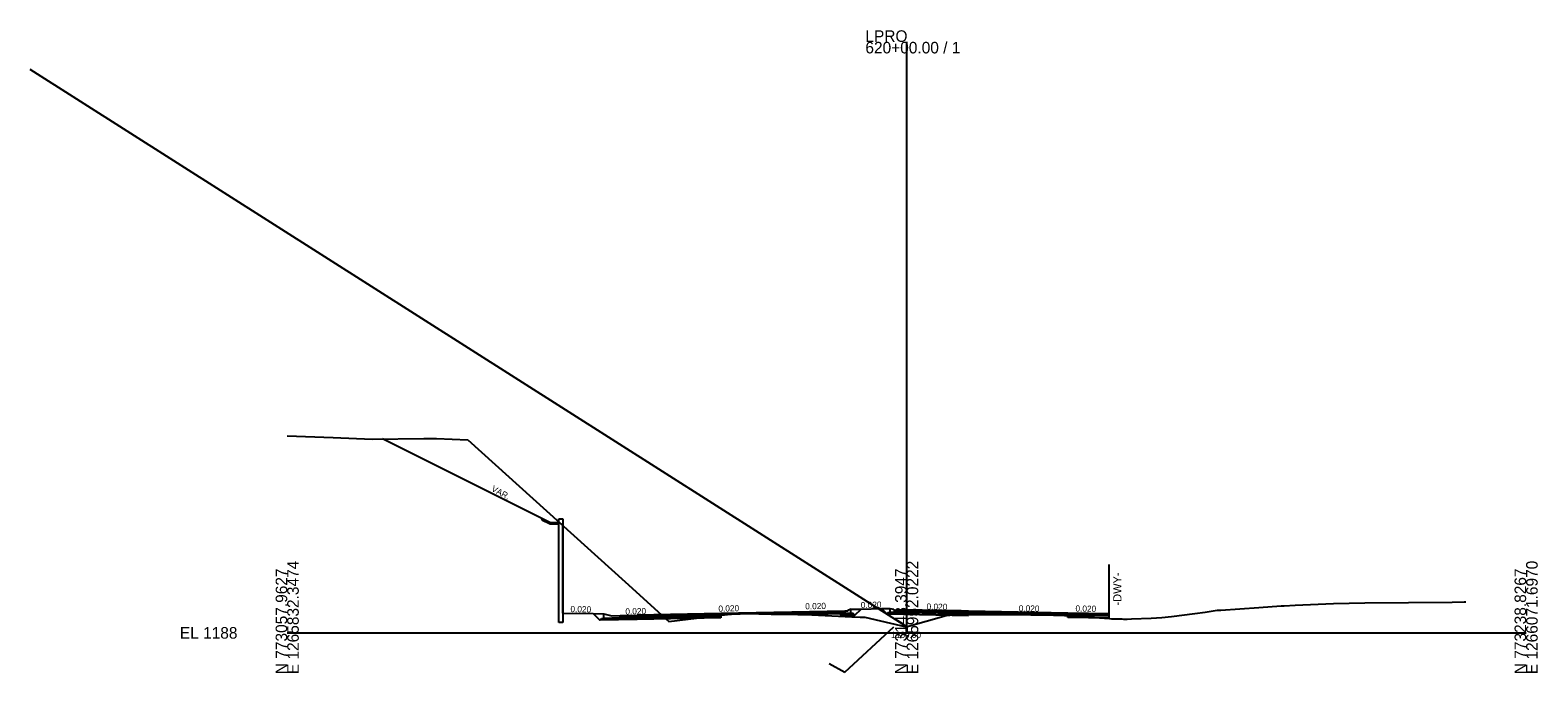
# Model space of a CAD drawing. Extents: x -3833 to 1267678, y -522 to 773248.
# Drawn here: x 2937.8 to 3302.8, y 990.3 to 1146.1 of the extents above; entities that cross this region are included whole.
import ezdxf

# ---------------------------------------------------------------- set-up
doc = ezdxf.new("R2010")
doc.units = 0
for name, color, linetype in [('Exist Cross Section Cell', 7, 'Continuous'), ('Exist XS Center Line Elevation Label', 7, 'Continuous'), ('Exist XS Ground Line', 7, 'Continuous'), ('Prop CMT DNC', 7, 'Continuous'), ('Prop CMT Pvmt Course 1', 7, 'Continuous'), ('Prop CMT Pvmt Course 2', 7, 'Continuous'), ('Prop CMT Pvmt Course 3', 7, 'Continuous'), ('Prop CMT Pvmt Course 4', 7, 'Continuous'), ('Prop CMT Shld Paved Course 1', 7, 'Continuous'), ('Prop CMT Shld Paved Course 2', 7, 'Continuous'), ('Prop CMT Shld Paved Course 4', 7, 'Continuous'), ('Prop CMT Slope Grass', 7, 'Continuous'), ('Prop CMT Subgrade Earthwork', 7, 'Continuous'), ('Prop Conc Curb and Gutter', 7, 'Continuous'), ('Prop Conc Island Cover', 7, 'Continuous'), ('Prop Corridor Mesh Bottom', 7, 'Continuous'), ('Prop XS Ditch Slope Text', 7, 'Continuous'), ('Prop XS Finish Grade', 7, 'Continuous'), ('Prop XS Label Text', 7, 'Continuous'), ('Prop XS SE Text', 7, 'Continuous'), ('Prop XS Shear Point Element', 7, 'Continuous'), ('Prop XS Shear Point Label', 7, 'Continuous'), ('Scratch_Level_1', 7, 'Continuous'), ('Scratch_Level_5', 7, 'Continuous')]:
    doc.layers.add(name, color=color, linetype=linetype)

msp = doc.modelspace()

# ---------------------------------------------------------------- linework, layer by layer
at = {"layer": 'Exist Cross Section Cell'}
for p, q in [((3150, 1000), (3150, 1143.25)), ((3000, 1000), (3150, 1000)), ((3150, 1000), (3300, 1000))]:
    msp.add_line(p, q, dxfattribs=at)
at = {"layer": 'Exist XS Ground Line'}
for p, q in [((3000, 1047.75), (3011.14, 1047.33)), ((3011.14, 1047.33), (3020.61, 1046.99)), ((3020.61, 1046.99), (3033.09, 1047.12)), ((3033.09, 1047.12), (3036.11, 1047.09)), ((3036.11, 1047.09), (3043.76, 1046.75)), ((3043.76, 1046.75), (3081.86, 1012.39)), ((3081.86, 1012.39), (3092.43, 1002.74)), ((3097.05, 1003.31), (3107.29, 1004.55)), ((3107.29, 1004.55), (3109.1, 1004.6)), ((3109.1, 1004.6), (3111.2, 1004.66)), ((3111.2, 1004.66), (3117.18, 1004.57)), ((3117.18, 1004.57), (3123.93, 1004.46)), ((3123.93, 1004.46), (3127.07, 1004.35)), ((3127.07, 1004.35), (3136.72, 1003.92)), ((3149.84, 1001.46), (3159.58, 1004.21)), ((3159.58, 1004.21), (3160.47, 1004.3)), ((3160.47, 1004.3), (3163.04, 1004.39)), ((3163.04, 1004.39), (3163.99, 1004.42)), ((3163.99, 1004.42), (3173.1, 1004.49)), ((3173.1, 1004.49), (3176.01, 1004.49)), ((3176.01, 1004.49), (3185.56, 1004.26)), ((3185.56, 1004.26), (3188.2, 1004.19)), ((3188.2, 1004.19), (3199.08, 1003.48)), ((3214.11, 1003.98), (3219.76, 1004.67)), ((3219.76, 1004.67), (3222.29, 1005)), ((3222.29, 1005), (3224.73, 1005.42)), ((3224.73, 1005.42), (3225.22, 1005.48)), ((3225.22, 1005.48), (3226.1, 1005.53)), ((3226.1, 1005.53), (3235.25, 1006.18)), ((3235.25, 1006.18), (3240.68, 1006.53)), ((3240.68, 1006.53), (3241.44, 1006.56)), ((3241.44, 1006.56), (3244.07, 1006.68)), ((3244.07, 1006.68), (3253.37, 1007.09)), ((3253.37, 1007.09), (3260.93, 1007.25)), ((3260.93, 1007.25), (3282.07, 1007.46)), ((3282.07, 1007.46), (3285.03, 1007.5)), ((3285.03, 1007.5), (3285.44, 1007.51)), ((3092.43, 1002.74), (3097.05, 1003.31)), ((3136.72, 1003.92), (3137.2, 1003.89)), ((3137.2, 1003.89), (3138.77, 1003.77)), ((3138.77, 1003.77), (3139.86, 1003.77)), ((3139.86, 1003.77), (3149.84, 1001.46)), ((3199.08, 1003.48), (3199.63, 1003.44)), ((3199.63, 1003.44), (3202.11, 1003.4)), ((3202.11, 1003.4), (3202.53, 1003.36)), ((3202.53, 1003.36), (3203.38, 1003.35)), ((3203.38, 1003.35), (3204.48, 1003.4)), ((3204.48, 1003.4), (3209.22, 1003.53)), ((3209.22, 1003.53), (3211.8, 1003.75)), ((3211.8, 1003.75), (3214.11, 1003.98))]:
    msp.add_line(p, q, dxfattribs=at)
at = {"layer": 'Prop CMT Pvmt Course 1'}
for p, q in [((3135, 1005.28), (3105, 1004.68)), ((3105, 1004.68), (3105, 1004.68)), ((3105, 1004.68), (3105, 1004.43)), ((3105, 1004.43), (3106.97, 1004.52)), ((3105, 1004.43), (3105, 1004.43)), ((3105, 1004.43), (3105, 1004.43)), ((3106.97, 1004.52), (3107.62, 1004.57)), ((3107.62, 1004.57), (3109.7, 1004.62)), ((3109.7, 1004.62), (3135, 1005.03)), ((3135, 1005.03), (3135, 1005.28)), ((3135, 1005.03), (3135, 1005.03)), ((3161.27, 1005.35), (3161.27, 1005.27)), ((3161.38, 1005.35), (3161.27, 1005.35)), ((3161.27, 1005.27), (3161.27, 1005.1)), ((3161.27, 1005.1), (3161.38, 1005.1)), ((3161.4, 1005.35), (3161.38, 1005.35)), ((3161.38, 1005.1), (3161.4, 1005.1)), ((3161.8, 1005.35), (3161.4, 1005.35)), ((3161.4, 1005.1), (3161.8, 1005.1)), ((3161.84, 1005.35), (3161.8, 1005.35)), ((3161.8, 1005.1), (3161.84, 1005.1)), ((3162.05, 1005.34), (3161.84, 1005.35)), ((3161.84, 1005.1), (3162.05, 1005.09)), ((3162.17, 1005.34), (3162.05, 1005.34)), ((3162.05, 1005.09), (3162.17, 1005.09)), ((3162.7, 1005.33), (3162.17, 1005.34)), ((3162.17, 1005.09), (3162.7, 1005.08)), ((3162.75, 1005.33), (3162.7, 1005.33)), ((3162.7, 1005.08), (3162.75, 1005.08)), ((3163.03, 1005.32), (3162.75, 1005.33)), ((3162.75, 1005.08), (3163.03, 1005.07)), ((3163.04, 1005.32), (3163.03, 1005.32)), ((3163.03, 1005.07), (3163.04, 1005.07)), ((3163.12, 1005.31), (3163.04, 1005.32)), ((3163.04, 1005.07), (3163.12, 1005.06)), ((3163.14, 1005.31), (3163.12, 1005.31)), ((3163.12, 1005.06), (3163.14, 1005.06)), ((3163.22, 1005.31), (3163.14, 1005.31)), ((3163.14, 1005.06), (3163.22, 1005.06)), ((3163.22, 1005.1), (3163.22, 1005.31)), ((3163.22, 1005.06), (3163.22, 1005.1)), ((3189, 1004.8), (3165, 1005.28)), ((3165, 1005.28), (3165, 1005.03)), ((3165, 1005.03), (3165, 1005.03)), ((3165, 1005.03), (3189, 1004.55)), ((3189, 1004.55), (3189, 1004.8)), ((3189, 1004.8), (3189, 1004.8)), ((3189, 1004.55), (3189, 1004.55)), ((3189, 1004.55), (3189, 1004.55))]:
    msp.add_line(p, q, dxfattribs=at)
at = {"layer": 'Prop CMT Pvmt Course 2'}
for p, q in [((3135, 1005.03), (3135, 1005.03)), ((3135, 1005.03), (3135, 1004.7)), ((3135, 1004.7), (3135, 1004.7)), ((3135, 1004.7), (3135, 1004.69)), ((3135, 1004.69), (3135, 1004.69)), ((3150, 1005.33), (3147.54, 1005.28)), ((3147.54, 1004.94), (3150, 1005)), ((3165, 1005.03), (3150, 1005.33)), ((3150, 1005), (3165, 1004.69)), ((3161.27, 1005.1), (3161.27, 1005.02)), ((3161.38, 1005.1), (3161.27, 1005.1)), ((3161.27, 1005.02), (3161.27, 1004.85)), ((3161.4, 1005.1), (3161.38, 1005.1)), ((3161.8, 1005.1), (3161.4, 1005.1)), ((3161.84, 1005.1), (3161.8, 1005.1)), ((3162.05, 1005.09), (3161.84, 1005.1)), ((3162.17, 1005.09), (3162.05, 1005.09)), ((3162.7, 1005.08), (3162.17, 1005.09)), ((3162.75, 1005.08), (3162.7, 1005.08)), ((3163.03, 1005.07), (3162.75, 1005.08)), ((3163.04, 1005.07), (3163.03, 1005.07)), ((3163.12, 1005.06), (3163.04, 1005.07)), ((3163.14, 1005.06), (3163.12, 1005.06)), ((3163.22, 1005.06), (3163.14, 1005.06)), ((3163.22, 1004.85), (3163.22, 1005.06)), ((3163.22, 1004.81), (3163.22, 1004.85)), ((3165, 1004.69), (3165, 1005.03)), ((3165, 1005.03), (3165, 1005.03)), ((3165, 1004.69), (3165, 1004.69)), ((3165, 1004.69), (3165, 1004.69)), ((3165, 1004.69), (3165, 1004.69))]:
    msp.add_line(p, q, dxfattribs=at)
at = {"layer": 'Prop CMT Pvmt Course 3'}
for p, q in [((3137.01, 1004.73), (3135, 1004.69)), ((3137.46, 1004.28), (3137.01, 1004.73)), ((3145.25, 1004.7), (3145.53, 1004.98)), ((3145.53, 1004.98), (3147.54, 1004.94)), ((3161.27, 1004.85), (3161.27, 1004.74)), ((3161.27, 1004.74), (3161.27, 1004.47)), ((3163.22, 1004.5), (3163.22, 1004.81)), ((3163.22, 1004.44), (3163.22, 1004.5))]:
    msp.add_line(p, q, dxfattribs=at)
at = {"layer": 'Prop CMT Pvmt Course 4'}
for p, q in [((3134, 1005.26), (3134, 1004.04)), ((3134, 1004.21), (3137.46, 1004.28)), ((3135, 1004.69), (3135, 1004.69)), ((3145.53, 1004.98), (3145.18, 1004.63)), ((3145.18, 1004.63), (3164.99, 1004.23)), ((3145.53, 1004.98), (3145.53, 1004.98)), ((3150, 1005), (3147.54, 1004.94)), ((3165, 1004.69), (3150, 1005)), ((3161.27, 1004.47), (3161.27, 1004.31)), ((3163.22, 1004.27), (3163.22, 1004.44)), ((3165, 1004.23), (3165, 1004.69)), ((3165, 1004.69), (3165, 1004.69)), ((3165, 1004.69), (3165, 1004.69))]:
    msp.add_line(p, q, dxfattribs=at)
at = {"layer": 'Prop CMT Shld Paved Course 1'}
for p, q in [((3080.64, 1004.19), (3084.74, 1004.27)), ((3080.64, 1003.94), (3080.64, 1004.19)), ((3080.64, 1004.19), (3080.64, 1004.19)), ((3084.74, 1004.02), (3080.64, 1003.94)), ((3105, 1004.68), (3084.74, 1004.27)), ((3084.74, 1004.02), (3105, 1004.43)), ((3084.74, 1004.27), (3084.74, 1004.02)), ((3084.74, 1004.27), (3084.74, 1004.02)), ((3084.74, 1004.02), (3084.74, 1004.02)), ((3105, 1004.43), (3105, 1004.68)), ((3135, 1005.28), (3135, 1005.28)), ((3135, 1005.28), (3135, 1005.03)), ((3135, 1005.03), (3135, 1005.03)), ((3135, 1005.03), (3135, 1005.03)), ((3150, 1005.58), (3147.54, 1005.53)), ((3147.54, 1005.28), (3150, 1005.33)), ((3165, 1005.28), (3150, 1005.58)), ((3150, 1005.33), (3165, 1005.03)), ((3165, 1005.03), (3165, 1005.28)), ((3165, 1005.28), (3165, 1005.28)), ((3165, 1005.03), (3165, 1005.03)), ((3165, 1005.03), (3165, 1005.03)), ((3199, 1004.6), (3189, 1004.8)), ((3080.64, 1003.94), (3080.64, 1003.94)), ((3080.64, 1003.94), (3080.64, 1003.94))]:
    msp.add_line(p, q, dxfattribs=at)
at = {"layer": 'Prop CMT Shld Paved Course 2'}
for p, q in [((3080.64, 1003.94), (3084.74, 1004.02)), ((3105, 1004.43), (3084.74, 1004.02)), ((3084.74, 1003.69), (3105, 1004.09)), ((3084.74, 1004.02), (3084.74, 1003.69)), ((3084.74, 1004.02), (3084.74, 1003.69)), ((3106.38, 1004.49), (3105, 1004.43)), ((3105, 1004.27), (3106.48, 1004.46)), ((3105, 1004.09), (3105, 1004.43)), ((3105, 1004.43), (3105, 1004.43)), ((3105, 1004.43), (3105, 1004.27)), ((3105, 1004.27), (3105, 1004.27)), ((3105, 1004.27), (3105, 1004.27)), ((3107.52, 1004.62), (3106.38, 1004.49)), ((3106.38, 1004.49), (3107.52, 1004.62)), ((3106.48, 1004.46), (3106.48, 1004.46)), ((3106.48, 1004.46), (3106.48, 1004.46)), ((3110.75, 1004.68), (3107.52, 1004.62)), ((3107.52, 1004.62), (3110.75, 1004.68)), ((3111.99, 1004.67), (3110.75, 1004.68)), ((3110.75, 1004.68), (3111.99, 1004.67)), ((3117.18, 1004.67), (3111.99, 1004.67)), ((3111.99, 1004.67), (3111.99, 1004.67)), ((3111.99, 1004.67), (3114.34, 1004.61)), ((3114.34, 1004.61), (3114.34, 1004.61)), ((3114.34, 1004.61), (3117.18, 1004.57)), ((3123.93, 1004.8), (3117.18, 1004.67)), ((3117.18, 1004.67), (3117.18, 1004.67)), ((3117.18, 1004.57), (3117.18, 1004.57)), ((3117.18, 1004.57), (3119.47, 1004.53)), ((3119.47, 1004.53), (3123.61, 1004.46)), ((3123.61, 1004.46), (3123.93, 1004.47)), ((3127.07, 1004.87), (3123.93, 1004.8)), ((3123.93, 1004.47), (3127.07, 1004.53)), ((3135, 1005.03), (3127.07, 1004.87)), ((3127.07, 1004.87), (3127.07, 1004.87)), ((3127.07, 1004.53), (3135, 1004.69)), ((3127.07, 1004.53), (3127.07, 1004.53)), ((3135, 1005.03), (3135, 1005.03)), ((3135, 1004.69), (3135, 1004.69)), ((3135, 1004.69), (3135, 1004.69)), ((3173.1, 1004.86), (3165, 1005.03)), ((3165, 1005.03), (3165, 1005.03)), ((3165, 1005.03), (3165, 1004.69)), ((3165, 1004.69), (3165, 1004.69)), ((3165, 1004.69), (3165, 1004.69)), ((3165, 1004.69), (3173.1, 1004.53)), ((3176.01, 1004.81), (3173.1, 1004.86)), ((3173.1, 1004.86), (3173.1, 1004.86)), ((3173.1, 1004.53), (3173.1, 1004.53)), ((3173.1, 1004.53), (3175.19, 1004.49)), ((3175.19, 1004.49), (3175.19, 1004.49)), ((3175.19, 1004.49), (3176.01, 1004.49)), ((3185.56, 1004.61), (3176.01, 1004.81)), ((3176.01, 1004.81), (3176.01, 1004.81)), ((3176.01, 1004.49), (3180.05, 1004.39)), ((3180.05, 1004.39), (3180.05, 1004.39)), ((3180.05, 1004.39), (3185.56, 1004.28)), ((3188.2, 1004.56), (3185.56, 1004.61)), ((3185.56, 1004.61), (3185.56, 1004.61)), ((3185.56, 1004.28), (3185.56, 1004.28)), ((3185.56, 1004.28), (3185.56, 1004.28)), ((3185.56, 1004.28), (3188.2, 1004.23)), ((3189, 1004.55), (3188.2, 1004.56)), ((3188.2, 1004.56), (3188.2, 1004.56)), ((3188.2, 1004.23), (3188.2, 1004.23)), ((3188.2, 1004.23), (3189, 1004.21)), ((3189, 1004.14), (3189, 1004.55)), ((3199, 1004.35), (3189, 1004.55)), ((3189, 1004.21), (3189, 1004.21)), ((3080.64, 1003.6), (3080.64, 1003.94)), ((3084.74, 1003.69), (3080.64, 1003.6))]:
    msp.add_line(p, q, dxfattribs=at)
at = {"layer": 'Prop CMT Shld Paved Course 4'}
for p, q in [((3084.74, 1003.69), (3105, 1004.09)), ((3105, 1004.09), (3105, 1003.63)), ((3199, 1004.02), (3189, 1004.21)), ((3075.67, 1003.05), (3076.14, 1003.51)), ((3084.74, 1003.23), (3075.67, 1003.05)), ((3076.14, 1003.51), (3076.64, 1003.52)), ((3076.64, 1003.52), (3084.74, 1003.69)), ((3084.74, 1003.23), (3084.74, 1003.69)), ((3084.74, 1003.69), (3084.74, 1003.23)), ((3105, 1003.63), (3084.74, 1003.23))]:
    msp.add_line(p, q, dxfattribs=at)
at = {"layer": 'Prop CMT Slope Grass'}
for p, q in [((3074.06, 1004.66), (3076.64, 1004.61)), ((3136.51, 1005.71), (3138.95, 1005.77)), ((3143.92, 1005.9), (3145.89, 1005.95))]:
    msp.add_line(p, q, dxfattribs=at)
at = {"layer": 'Prop CMT Subgrade Earthwork'}
for p, q in [((3074.06, 1004.66), (3075.67, 1003.05)), ((3105, 1003.63), (3105, 1004.27)), ((3137.46, 1004.28), (3134, 1004.21)), ((3134, 1004.21), (3134, 1004.04)), ((3137.46, 1004.28), (3138.95, 1005.77)), ((3145.18, 1004.63), (3143.92, 1005.9)), ((3165, 1004.23), (3145.18, 1004.63)), ((3165, 1004.23), (3165, 1004.43)), ((3189, 1003.76), (3189, 1004.14)), ((3105, 1003.63), (3075.67, 1003.05)), ((3199, 1003.56), (3189, 1003.76)), ((3199, 1003.49), (3199, 1003.56))]:
    msp.add_line(p, q, dxfattribs=at)
at = {"layer": 'Prop Conc Curb and Gutter'}
for p, q in [((3061.69, 1027.34), (3061.84, 1027.64)), ((3063.69, 1026.34), (3061.69, 1027.34)), ((3063.77, 1026.67), (3061.84, 1027.64)), ((3065.77, 1026.34), (3063.69, 1026.34)), ((3065.77, 1026.67), (3063.77, 1026.67)), ((3065.76, 1002.52), (3065.77, 1027.67)), ((3065.77, 1027.67), (3065.77, 1027.67)), ((3065.77, 1027.67), (3066.77, 1027.67)), ((3066.77, 1027.67), (3066.77, 1027.67)), ((3066.77, 1027.67), (3066.77, 1003.91)), ((3076.64, 1003.52), (3076.64, 1004.61)), ((3076.64, 1004.61), (3078.64, 1004.11)), ((3078.64, 1004.11), (3080.64, 1004.19)), ((3078.64, 1004.11), (3078.64, 1004.11)), ((3078.64, 1004.11), (3078.64, 1004.11)), ((3080.64, 1004.19), (3080.64, 1003.6)), ((3135.75, 1005.29), (3135, 1005.28)), ((3135, 1005.28), (3135, 1005.28)), ((3135, 1005.28), (3135, 1004.69)), ((3135, 1004.69), (3136.51, 1004.72)), ((3135, 1004.69), (3135, 1004.69)), ((3135, 1004.69), (3135, 1004.69)), ((3136.51, 1005.71), (3135.75, 1005.46)), ((3135.75, 1005.46), (3135.75, 1005.46)), ((3135.75, 1005.46), (3135.75, 1005.29)), ((3135.75, 1005.29), (3135.75, 1005.29)), ((3136.51, 1004.72), (3136.51, 1005.71)), ((3136.51, 1004.72), (3136.51, 1004.72)), ((3146.03, 1004.98), (3146.03, 1005.96)), ((3146.03, 1005.96), (3146.04, 1005.95)), ((3146.03, 1004.97), (3146.03, 1004.98)), ((3146.05, 1004.97), (3146.03, 1004.97)), ((3146.04, 1005.95), (3146.79, 1005.71)), ((3147.54, 1004.94), (3146.05, 1004.97)), ((3146.79, 1005.71), (3146.79, 1005.54)), ((3146.79, 1005.54), (3146.79, 1005.54)), ((3146.79, 1005.54), (3146.8, 1005.54)), ((3146.8, 1005.54), (3147.54, 1005.53)), ((3147.54, 1005.53), (3147.54, 1004.94)), ((3147.54, 1004.94), (3147.54, 1004.94)), ((3066.77, 1002.52), (3065.76, 1002.52)), ((3065.76, 1002.52), (3065.76, 1002.52)), ((3065.76, 1002.52), (3065.76, 1002.52)), ((3066.77, 1003.91), (3066.77, 1002.52)), ((3066.77, 1002.52), (3066.77, 1002.52)), ((3078.64, 1003.56), (3076.64, 1003.52)), ((3076.64, 1003.52), (3076.64, 1003.52)), ((3076.64, 1003.52), (3076.64, 1003.52)), ((3080.64, 1003.6), (3078.64, 1003.56)), ((3078.64, 1003.56), (3078.64, 1003.56)), ((3080.64, 1003.6), (3080.64, 1003.6))]:
    msp.add_line(p, q, dxfattribs=at)
at = {"layer": 'Prop Conc Island Cover'}
for p, q in [((3136.51, 1005.46), (3136.51, 1005.71)), ((3146.03, 1005.96), (3146.03, 1005.71))]:
    msp.add_line(p, q, dxfattribs=at)
at = {"layer": 'Prop Corridor Mesh Bottom'}
for p, q in [((3084.74, 1004.27), (3084.74, 1004.02)), ((3135, 1005.28), (3135, 1005.03)), ((3165, 1005.28), (3165, 1005.03)), ((3189, 1004.8), (3189, 1004.55))]:
    msp.add_line(p, q, dxfattribs=at)
at = {"layer": 'Prop XS Finish Grade'}
for p, q in [((3061.84, 1027.64), (3023.08, 1047.01)), ((3063.77, 1026.67), (3061.84, 1027.64)), ((3065.77, 1026.67), (3063.77, 1026.67)), ((3066.77, 1026), (3065.77, 1026.91)), ((3065.77, 1026.91), (3065.77, 1026.67)), ((3066.77, 1004.81), (3066.77, 1026)), ((3066.77, 1004.81), (3074.06, 1004.66)), ((3138.95, 1005.77), (3143.92, 1005.9)), ((3145.89, 1005.95), (3146.03, 1005.96))]:
    msp.add_line(p, q, dxfattribs=at)
at = {"layer": 'Prop XS Shear Point Element'}
msp.add_line((3199, 1003.49), (3199, 1016.57), dxfattribs=at)
at = {"layer": 'Scratch_Level_1'}
msp.add_line((3150, 1001.5), (2937.75, 1136.56), dxfattribs=at)
at = {"layer": 'Scratch_Level_5'}
for p, q in [((3135.06, 990.45), (3146.92, 1001.48)), ((3131.27, 992.56), (3135.06, 990.45))]:
    msp.add_line(p, q, dxfattribs=at)

# ---------------------------------------------------------------- texts
at = {"layer": 'Exist Cross Section Cell'}
for s, p in [('620+00.00 / 1', (3140, 1140.45)), ('LPRO', (3140, 1143.25)), ('EL 1188', (2974, 998.6))]:
    msp.add_text(s, height=2.8, dxfattribs=at).set_placement(p)
for s, p in [('N 773057.9627', (3000, 990)), ('E 1265832.3474', (3002.8, 990)), ('N 773148.3947', (3150, 990)), ('E 1265952.0222', (3152.8, 990)), ('N 773238.8267', (3300, 990)), ('E 1266071.6970', (3302.8, 990))]:
    msp.add_text(s, height=2.8, rotation=90, dxfattribs=at).set_placement(p)
at = {"layer": 'Exist XS Center Line Elevation Label'}
msp.add_text('1189.50', height=1.5, dxfattribs=at).set_placement((3146.25, 998.79))
at = {"layer": 'Prop CMT DNC'}
for p in [(3077.64, 1016.2), (3080.64, 1004.19), (3080.64, 1004.19), (3084.74, 1004.27), (3084.74, 1004.27), (3135, 1005.28), (3135, 1005.28), (3135.75, 1005.29), (3146.79, 1005.54), (3150, 1005.58), (3165, 1005.28), (3165, 1005.28), (3189, 1004.8), (3189, 1004.8), (3199, 1004.6)]:
    msp.add_text('X', height=0.00025, dxfattribs=at).set_placement(p)
at = {"layer": 'Prop XS Ditch Slope Text'}
msp.add_text('VAR.', height=1.5, rotation=331.3485, dxfattribs=at).set_placement((3049.31, 1034.47))
at = {"layer": 'Prop XS Label Text'}
msp.add_text('0.020', height=0.15, rotation=358.8542, dxfattribs=at).set_placement((3157.29, 1006.13))
at = {"layer": 'Prop XS SE Text'}
for rotation, p in [(358.8542, (3068.57, 1005.04)), (1.397, (3081.9, 1004.43)), (1.397, (3104.43, 1005.12)), (1.299, (3125.45, 1005.69)), (1.26, (3138.9, 1005.99)), (358.8542, (3154.81, 1005.64)), (358.8542, (3177.12, 1005.22)), (358.8542, (3190.86, 1005.18))]:
    msp.add_text('0.020', height=1.5, rotation=rotation, dxfattribs=at).set_placement(p)
at = {"layer": 'Prop XS Shear Point Label'}
msp.add_text('-DWY-', height=2, rotation=90, dxfattribs=at).set_placement((3202.01, 1006.63))

doc.saveas('drawing.dxf')
